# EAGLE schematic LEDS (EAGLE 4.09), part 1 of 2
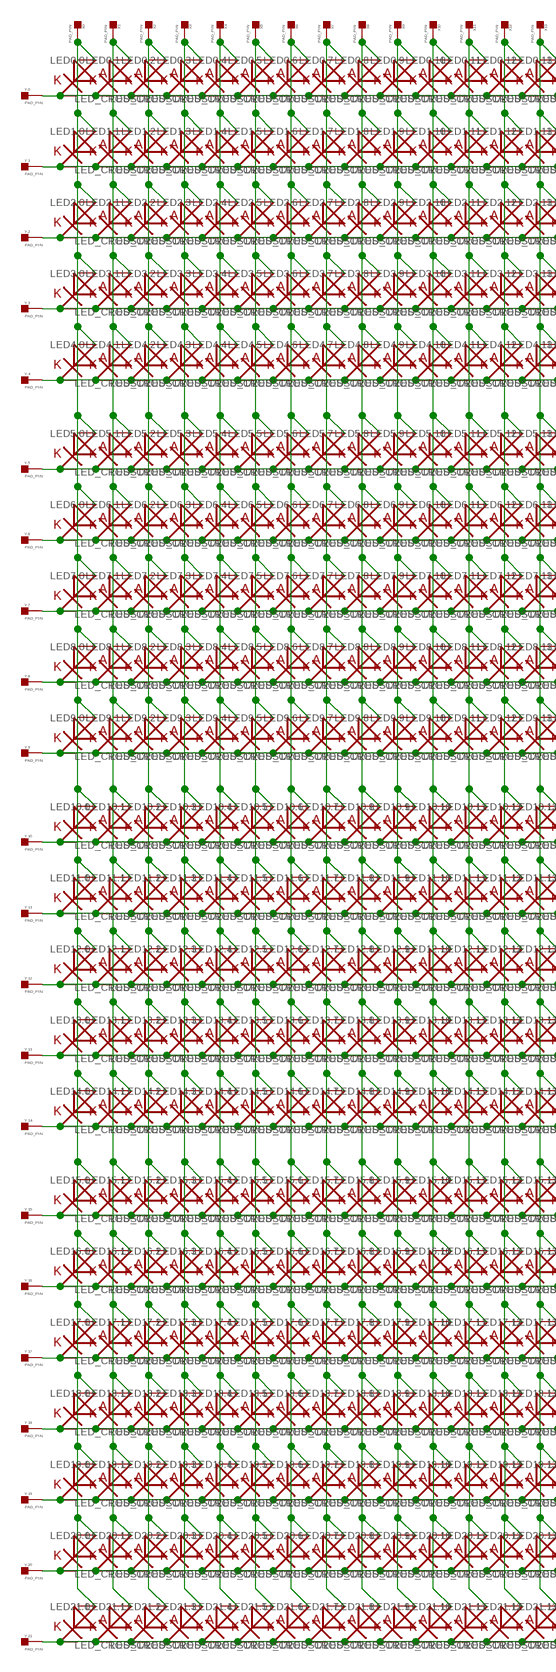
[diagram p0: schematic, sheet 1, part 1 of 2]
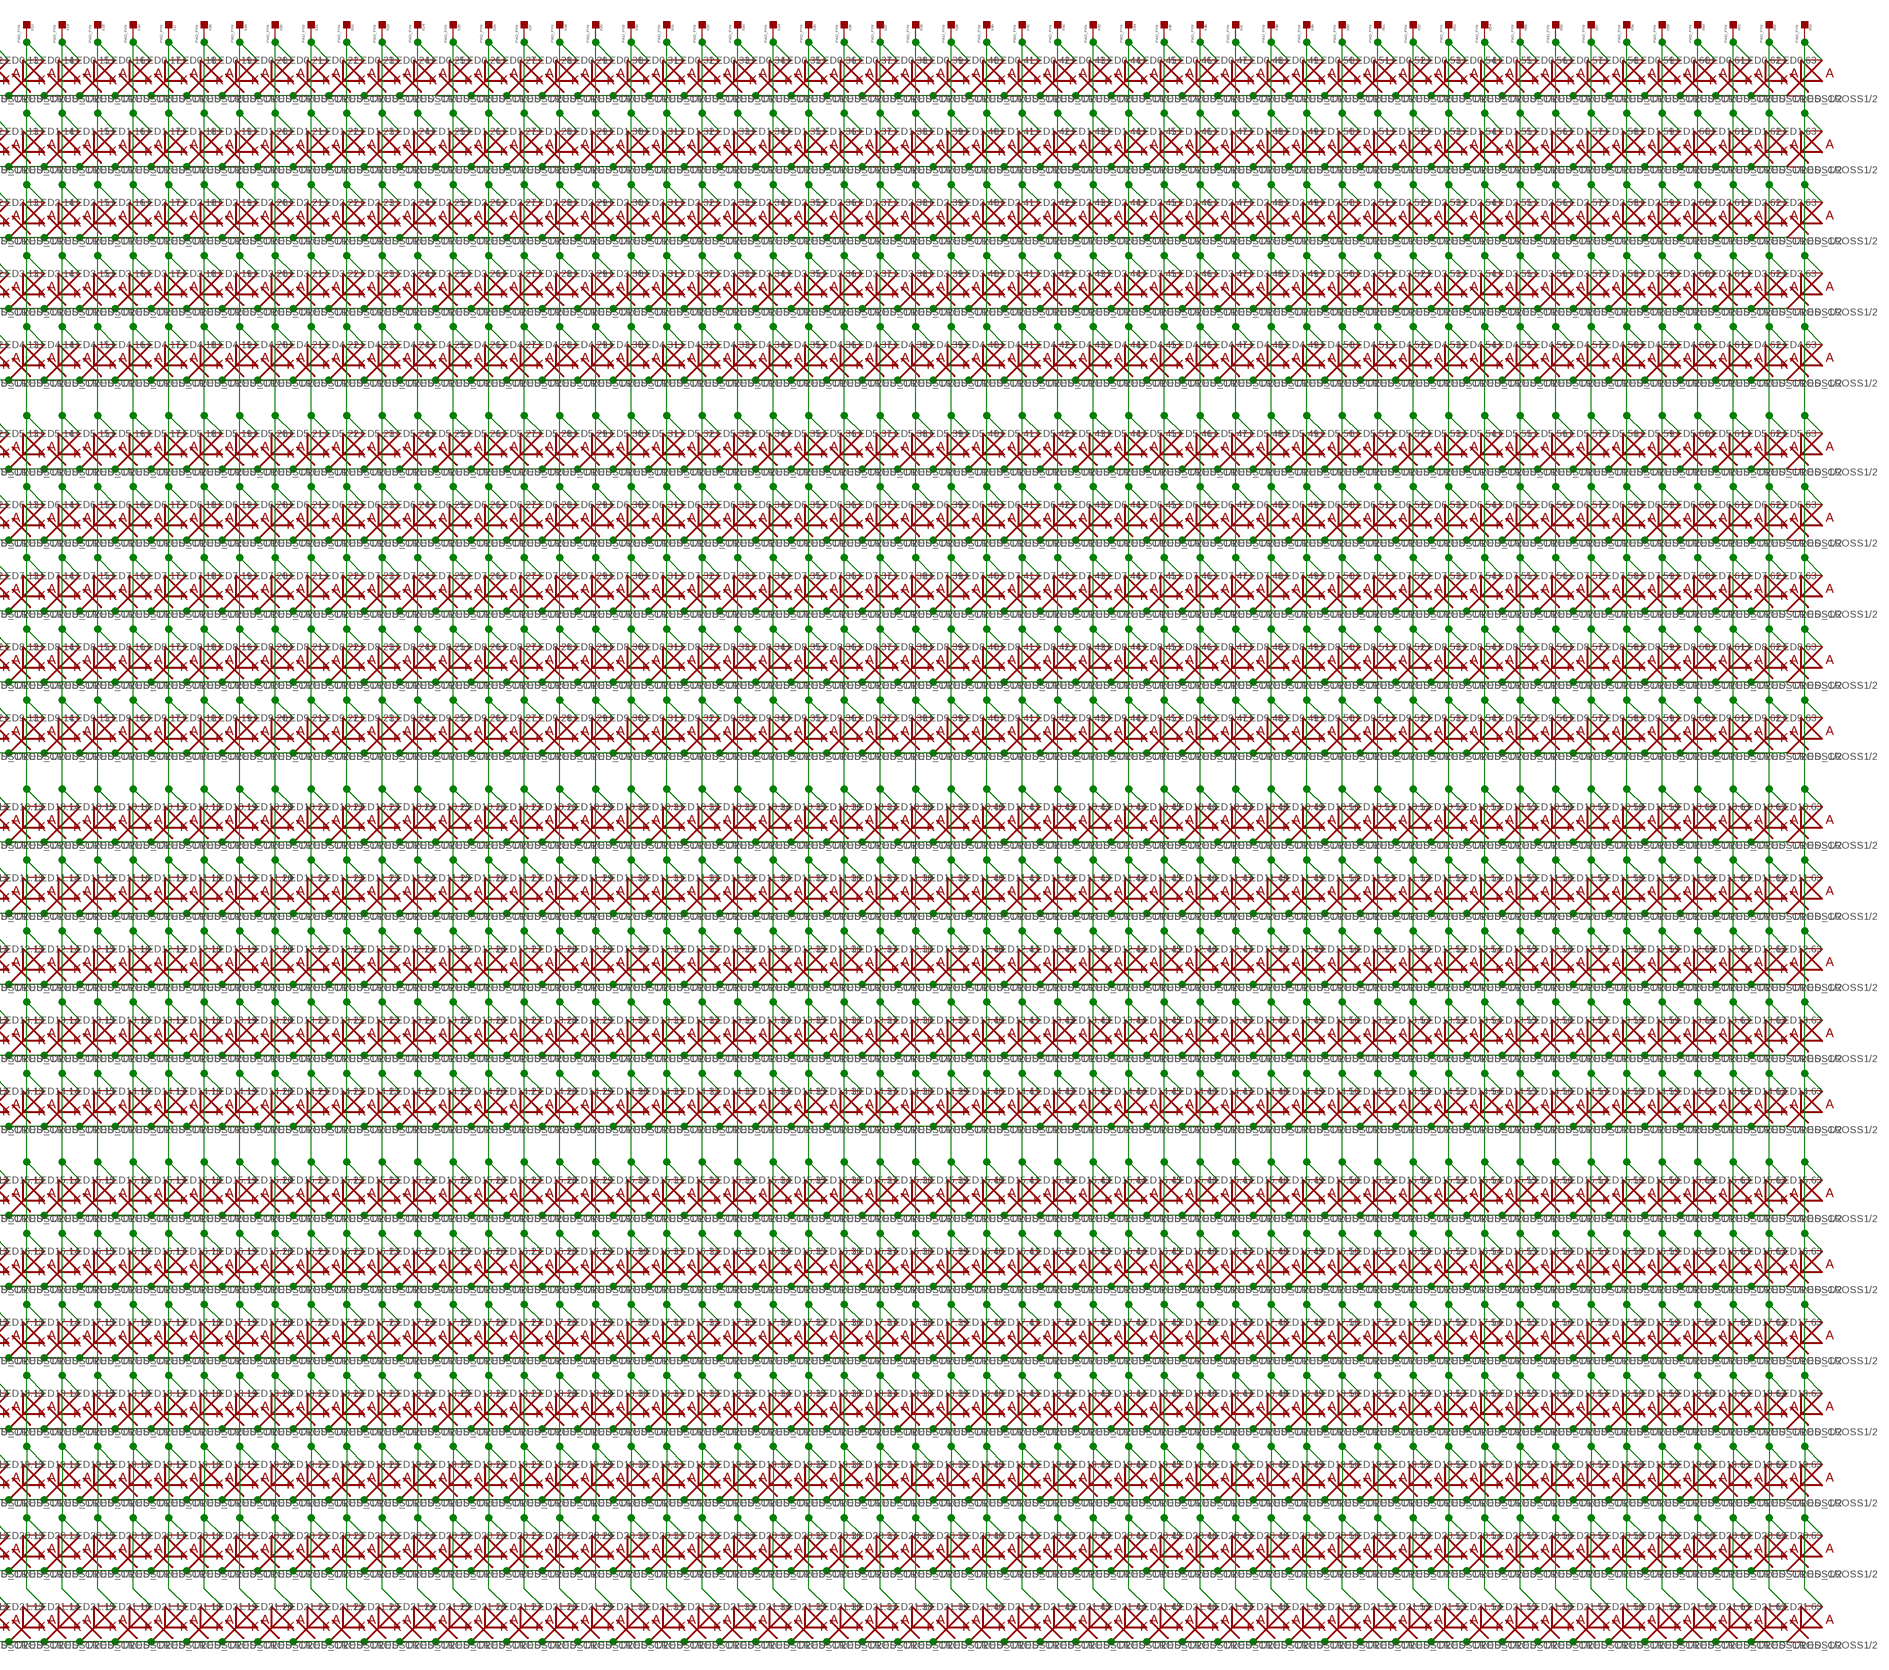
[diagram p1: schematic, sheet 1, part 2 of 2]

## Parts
LED0.0  LED_CROSS1/2  [LED_603]
LED0.1  LED_CROSS1/2  [LED_603]
LED0.2  LED_CROSS1/2  [LED_603]
LED0.3  LED_CROSS1/2  [LED_603]
LED0.4  LED_CROSS1/2  [LED_603]
LED0.5  LED_CROSS1/2  [LED_603]
LED0.6  LED_CROSS1/2  [LED_603]
LED0.7  LED_CROSS1/2  [LED_603]
LED0.8  LED_CROSS1/2  [LED_603]
LED0.9  LED_CROSS1/2  [LED_603]
LED0.10  LED_CROSS1/2  [LED_603]
LED0.11  LED_CROSS1/2  [LED_603]
LED0.12  LED_CROSS1/2  [LED_603]
LED0.13  LED_CROSS1/2  [LED_603]
LED0.14  LED_CROSS1/2  [LED_603]
LED0.15  LED_CROSS1/2  [LED_603]
LED0.16  LED_CROSS1/2  [LED_603]
LED0.17  LED_CROSS1/2  [LED_603]
LED0.18  LED_CROSS1/2  [LED_603]
LED0.19  LED_CROSS1/2  [LED_603]
LED0.20  LED_CROSS1/2  [LED_603]
LED0.21  LED_CROSS1/2  [LED_603]
LED0.22  LED_CROSS1/2  [LED_603]
LED0.23  LED_CROSS1/2  [LED_603]
LED0.24  LED_CROSS1/2  [LED_603]
LED0.25  LED_CROSS1/2  [LED_603]
LED0.26  LED_CROSS1/2  [LED_603]
LED0.27  LED_CROSS1/2  [LED_603]
LED0.28  LED_CROSS1/2  [LED_603]
LED0.29  LED_CROSS1/2  [LED_603]
LED0.30  LED_CROSS1/2  [LED_603]
LED0.31  LED_CROSS1/2  [LED_603]
LED0.32  LED_CROSS1/2  [LED_603]
LED0.33  LED_CROSS1/2  [LED_603]
LED0.34  LED_CROSS1/2  [LED_603]
LED0.35  LED_CROSS1/2  [LED_603]
LED0.36  LED_CROSS1/2  [LED_603]
LED0.37  LED_CROSS1/2  [LED_603]
LED0.38  LED_CROSS1/2  [LED_603]
LED0.39  LED_CROSS1/2  [LED_603]
LED0.40  LED_CROSS1/2  [LED_603]
LED0.41  LED_CROSS1/2  [LED_603]
LED0.42  LED_CROSS1/2  [LED_603]
LED0.43  LED_CROSS1/2  [LED_603]
LED0.44  LED_CROSS1/2  [LED_603]
LED0.45  LED_CROSS1/2  [LED_603]
LED0.46  LED_CROSS1/2  [LED_603]
LED0.47  LED_CROSS1/2  [LED_603]
LED0.48  LED_CROSS1/2  [LED_603]
LED0.49  LED_CROSS1/2  [LED_603]
LED0.50  LED_CROSS1/2  [LED_603]
LED0.51  LED_CROSS1/2  [LED_603]
LED0.52  LED_CROSS1/2  [LED_603]
LED0.53  LED_CROSS1/2  [LED_603]
LED0.54  LED_CROSS1/2  [LED_603]
LED0.55  LED_CROSS1/2  [LED_603]
LED0.56  LED_CROSS1/2  [LED_603]
LED0.57  LED_CROSS1/2  [LED_603]
LED0.58  LED_CROSS1/2  [LED_603]
LED0.59  LED_CROSS1/2  [LED_603]
LED0.60  LED_CROSS1/2  [LED_603]
LED0.61  LED_CROSS1/2  [LED_603]
LED0.62  LED_CROSS1/2  [LED_603]
LED0.63  LED_CROSS1/2  [LED_603]
LED1.0  LED_CROSS1/2  [LED_603]
LED1.1  LED_CROSS1/2  [LED_603]
LED1.2  LED_CROSS1/2  [LED_603]
LED1.3  LED_CROSS1/2  [LED_603]
LED1.4  LED_CROSS1/2  [LED_603]
LED1.5  LED_CROSS1/2  [LED_603]
LED1.6  LED_CROSS1/2  [LED_603]
LED1.7  LED_CROSS1/2  [LED_603]
LED1.8  LED_CROSS1/2  [LED_603]
LED1.9  LED_CROSS1/2  [LED_603]
LED1.10  LED_CROSS1/2  [LED_603]
LED1.11  LED_CROSS1/2  [LED_603]
LED1.12  LED_CROSS1/2  [LED_603]
LED1.13  LED_CROSS1/2  [LED_603]
LED1.14  LED_CROSS1/2  [LED_603]
LED1.15  LED_CROSS1/2  [LED_603]
LED1.16  LED_CROSS1/2  [LED_603]
LED1.17  LED_CROSS1/2  [LED_603]
LED1.18  LED_CROSS1/2  [LED_603]
LED1.19  LED_CROSS1/2  [LED_603]
LED1.20  LED_CROSS1/2  [LED_603]
LED1.21  LED_CROSS1/2  [LED_603]
LED1.22  LED_CROSS1/2  [LED_603]
LED1.23  LED_CROSS1/2  [LED_603]
LED1.24  LED_CROSS1/2  [LED_603]
LED1.25  LED_CROSS1/2  [LED_603]
LED1.26  LED_CROSS1/2  [LED_603]
LED1.27  LED_CROSS1/2  [LED_603]
LED1.28  LED_CROSS1/2  [LED_603]
LED1.29  LED_CROSS1/2  [LED_603]
LED1.30  LED_CROSS1/2  [LED_603]
LED1.31  LED_CROSS1/2  [LED_603]
LED1.32  LED_CROSS1/2  [LED_603]
LED1.33  LED_CROSS1/2  [LED_603]
LED1.34  LED_CROSS1/2  [LED_603]
LED1.35  LED_CROSS1/2  [LED_603]
LED1.36  LED_CROSS1/2  [LED_603]
LED1.37  LED_CROSS1/2  [LED_603]
LED1.38  LED_CROSS1/2  [LED_603]
LED1.39  LED_CROSS1/2  [LED_603]
LED1.40  LED_CROSS1/2  [LED_603]
LED1.41  LED_CROSS1/2  [LED_603]
LED1.42  LED_CROSS1/2  [LED_603]
LED1.43  LED_CROSS1/2  [LED_603]
LED1.44  LED_CROSS1/2  [LED_603]
LED1.45  LED_CROSS1/2  [LED_603]
LED1.46  LED_CROSS1/2  [LED_603]
LED1.47  LED_CROSS1/2  [LED_603]
LED1.48  LED_CROSS1/2  [LED_603]
LED1.49  LED_CROSS1/2  [LED_603]
LED1.50  LED_CROSS1/2  [LED_603]
LED1.51  LED_CROSS1/2  [LED_603]
LED1.52  LED_CROSS1/2  [LED_603]
LED1.53  LED_CROSS1/2  [LED_603]
LED1.54  LED_CROSS1/2  [LED_603]
LED1.55  LED_CROSS1/2  [LED_603]
LED1.56  LED_CROSS1/2  [LED_603]
LED1.57  LED_CROSS1/2  [LED_603]
LED1.58  LED_CROSS1/2  [LED_603]
LED1.59  LED_CROSS1/2  [LED_603]
LED1.60  LED_CROSS1/2  [LED_603]
LED1.61  LED_CROSS1/2  [LED_603]
LED1.62  LED_CROSS1/2  [LED_603]
LED1.63  LED_CROSS1/2  [LED_603]
LED2.0  LED_CROSS1/2  [LED_603]
LED2.1  LED_CROSS1/2  [LED_603]
LED2.2  LED_CROSS1/2  [LED_603]
LED2.3  LED_CROSS1/2  [LED_603]
LED2.4  LED_CROSS1/2  [LED_603]
LED2.5  LED_CROSS1/2  [LED_603]
LED2.6  LED_CROSS1/2  [LED_603]
LED2.7  LED_CROSS1/2  [LED_603]
LED2.8  LED_CROSS1/2  [LED_603]
LED2.9  LED_CROSS1/2  [LED_603]
LED2.10  LED_CROSS1/2  [LED_603]
LED2.11  LED_CROSS1/2  [LED_603]
LED2.12  LED_CROSS1/2  [LED_603]
LED2.13  LED_CROSS1/2  [LED_603]
LED2.14  LED_CROSS1/2  [LED_603]
LED2.15  LED_CROSS1/2  [LED_603]
LED2.16  LED_CROSS1/2  [LED_603]
LED2.17  LED_CROSS1/2  [LED_603]
LED2.18  LED_CROSS1/2  [LED_603]
LED2.19  LED_CROSS1/2  [LED_603]
LED2.20  LED_CROSS1/2  [LED_603]
LED2.21  LED_CROSS1/2  [LED_603]
LED2.22  LED_CROSS1/2  [LED_603]
LED2.23  LED_CROSS1/2  [LED_603]
LED2.24  LED_CROSS1/2  [LED_603]
LED2.25  LED_CROSS1/2  [LED_603]
LED2.26  LED_CROSS1/2  [LED_603]
LED2.27  LED_CROSS1/2  [LED_603]
LED2.28  LED_CROSS1/2  [LED_603]
LED2.29  LED_CROSS1/2  [LED_603]
LED2.30  LED_CROSS1/2  [LED_603]
LED2.31  LED_CROSS1/2  [LED_603]
LED2.32  LED_CROSS1/2  [LED_603]
LED2.33  LED_CROSS1/2  [LED_603]
LED2.34  LED_CROSS1/2  [LED_603]
LED2.35  LED_CROSS1/2  [LED_603]
LED2.36  LED_CROSS1/2  [LED_603]
LED2.37  LED_CROSS1/2  [LED_603]
LED2.38  LED_CROSS1/2  [LED_603]
LED2.39  LED_CROSS1/2  [LED_603]
LED2.40  LED_CROSS1/2  [LED_603]
LED2.41  LED_CROSS1/2  [LED_603]
LED2.42  LED_CROSS1/2  [LED_603]
LED2.43  LED_CROSS1/2  [LED_603]
LED2.44  LED_CROSS1/2  [LED_603]
LED2.45  LED_CROSS1/2  [LED_603]
LED2.46  LED_CROSS1/2  [LED_603]
LED2.47  LED_CROSS1/2  [LED_603]
LED2.48  LED_CROSS1/2  [LED_603]
LED2.49  LED_CROSS1/2  [LED_603]
LED2.50  LED_CROSS1/2  [LED_603]
LED2.51  LED_CROSS1/2  [LED_603]
LED2.52  LED_CROSS1/2  [LED_603]
LED2.53  LED_CROSS1/2  [LED_603]
LED2.54  LED_CROSS1/2  [LED_603]
LED2.55  LED_CROSS1/2  [LED_603]
LED2.56  LED_CROSS1/2  [LED_603]
LED2.57  LED_CROSS1/2  [LED_603]
LED2.58  LED_CROSS1/2  [LED_603]
LED2.59  LED_CROSS1/2  [LED_603]
LED2.60  LED_CROSS1/2  [LED_603]
LED2.61  LED_CROSS1/2  [LED_603]
LED2.62  LED_CROSS1/2  [LED_603]
LED2.63  LED_CROSS1/2  [LED_603]
LED3.0  LED_CROSS1/2  [LED_603]
LED3.1  LED_CROSS1/2  [LED_603]
LED3.2  LED_CROSS1/2  [LED_603]
LED3.3  LED_CROSS1/2  [LED_603]
LED3.4  LED_CROSS1/2  [LED_603]
LED3.5  LED_CROSS1/2  [LED_603]
LED3.6  LED_CROSS1/2  [LED_603]
LED3.7  LED_CROSS1/2  [LED_603]
LED3.8  LED_CROSS1/2  [LED_603]
LED3.9  LED_CROSS1/2  [LED_603]
LED3.10  LED_CROSS1/2  [LED_603]
LED3.11  LED_CROSS1/2  [LED_603]
LED3.12  LED_CROSS1/2  [LED_603]
LED3.13  LED_CROSS1/2  [LED_603]
LED3.14  LED_CROSS1/2  [LED_603]
LED3.15  LED_CROSS1/2  [LED_603]
LED3.16  LED_CROSS1/2  [LED_603]
LED3.17  LED_CROSS1/2  [LED_603]
LED3.18  LED_CROSS1/2  [LED_603]
LED3.19  LED_CROSS1/2  [LED_603]
LED3.20  LED_CROSS1/2  [LED_603]
LED3.21  LED_CROSS1/2  [LED_603]
LED3.22  LED_CROSS1/2  [LED_603]
LED3.23  LED_CROSS1/2  [LED_603]
LED3.24  LED_CROSS1/2  [LED_603]
LED3.25  LED_CROSS1/2  [LED_603]
LED3.26  LED_CROSS1/2  [LED_603]
LED3.27  LED_CROSS1/2  [LED_603]
LED3.28  LED_CROSS1/2  [LED_603]
LED3.29  LED_CROSS1/2  [LED_603]
LED3.30  LED_CROSS1/2  [LED_603]
LED3.31  LED_CROSS1/2  [LED_603]
LED3.32  LED_CROSS1/2  [LED_603]
LED3.33  LED_CROSS1/2  [LED_603]
LED3.34  LED_CROSS1/2  [LED_603]
LED3.35  LED_CROSS1/2  [LED_603]
LED3.36  LED_CROSS1/2  [LED_603]
LED3.37  LED_CROSS1/2  [LED_603]
LED3.38  LED_CROSS1/2  [LED_603]
LED3.39  LED_CROSS1/2  [LED_603]
LED3.40  LED_CROSS1/2  [LED_603]
LED3.41  LED_CROSS1/2  [LED_603]
LED3.42  LED_CROSS1/2  [LED_603]
LED3.43  LED_CROSS1/2  [LED_603]
LED3.44  LED_CROSS1/2  [LED_603]
LED3.45  LED_CROSS1/2  [LED_603]
LED3.46  LED_CROSS1/2  [LED_603]
LED3.47  LED_CROSS1/2  [LED_603]
LED3.48  LED_CROSS1/2  [LED_603]
LED3.49  LED_CROSS1/2  [LED_603]
LED3.50  LED_CROSS1/2  [LED_603]
LED3.51  LED_CROSS1/2  [LED_603]
LED3.52  LED_CROSS1/2  [LED_603]
LED3.53  LED_CROSS1/2  [LED_603]
LED3.54  LED_CROSS1/2  [LED_603]
LED3.55  LED_CROSS1/2  [LED_603]
LED3.56  LED_CROSS1/2  [LED_603]
LED3.57  LED_CROSS1/2  [LED_603]
LED3.58  LED_CROSS1/2  [LED_603]
LED3.59  LED_CROSS1/2  [LED_603]
LED3.60  LED_CROSS1/2  [LED_603]
LED3.61  LED_CROSS1/2  [LED_603]
LED3.62  LED_CROSS1/2  [LED_603]
LED3.63  LED_CROSS1/2  [LED_603]
LED4.0  LED_CROSS1/2  [LED_603]
LED4.1  LED_CROSS1/2  [LED_603]
LED4.2  LED_CROSS1/2  [LED_603]
LED4.3  LED_CROSS1/2  [LED_603]
LED4.4  LED_CROSS1/2  [LED_603]
LED4.5  LED_CROSS1/2  [LED_603]
LED4.6  LED_CROSS1/2  [LED_603]
LED4.7  LED_CROSS1/2  [LED_603]
LED4.8  LED_CROSS1/2  [LED_603]
LED4.9  LED_CROSS1/2  [LED_603]
LED4.10  LED_CROSS1/2  [LED_603]
LED4.11  LED_CROSS1/2  [LED_603]
LED4.12  LED_CROSS1/2  [LED_603]
LED4.13  LED_CROSS1/2  [LED_603]
LED4.14  LED_CROSS1/2  [LED_603]
LED4.15  LED_CROSS1/2  [LED_603]
LED4.16  LED_CROSS1/2  [LED_603]
LED4.17  LED_CROSS1/2  [LED_603]
LED4.18  LED_CROSS1/2  [LED_603]
LED4.19  LED_CROSS1/2  [LED_603]
LED4.20  LED_CROSS1/2  [LED_603]
LED4.21  LED_CROSS1/2  [LED_603]
LED4.22  LED_CROSS1/2  [LED_603]
LED4.23  LED_CROSS1/2  [LED_603]
LED4.24  LED_CROSS1/2  [LED_603]
LED4.25  LED_CROSS1/2  [LED_603]
LED4.26  LED_CROSS1/2  [LED_603]
LED4.27  LED_CROSS1/2  [LED_603]
LED4.28  LED_CROSS1/2  [LED_603]
LED4.29  LED_CROSS1/2  [LED_603]
LED4.30  LED_CROSS1/2  [LED_603]
LED4.31  LED_CROSS1/2  [LED_603]
LED4.32  LED_CROSS1/2  [LED_603]
LED4.33  LED_CROSS1/2  [LED_603]
LED4.34  LED_CROSS1/2  [LED_603]
LED4.35  LED_CROSS1/2  [LED_603]
LED4.36  LED_CROSS1/2  [LED_603]
LED4.37  LED_CROSS1/2  [LED_603]
LED4.38  LED_CROSS1/2  [LED_603]
LED4.39  LED_CROSS1/2  [LED_603]
LED4.40  LED_CROSS1/2  [LED_603]
LED4.41  LED_CROSS1/2  [LED_603]
LED4.42  LED_CROSS1/2  [LED_603]
LED4.43  LED_CROSS1/2  [LED_603]
LED4.44  LED_CROSS1/2  [LED_603]
LED4.45  LED_CROSS1/2  [LED_603]
LED4.46  LED_CROSS1/2  [LED_603]
LED4.47  LED_CROSS1/2  [LED_603]
LED4.48  LED_CROSS1/2  [LED_603]
LED4.49  LED_CROSS1/2  [LED_603]
LED4.50  LED_CROSS1/2  [LED_603]
LED4.51  LED_CROSS1/2  [LED_603]
LED4.52  LED_CROSS1/2  [LED_603]
LED4.53  LED_CROSS1/2  [LED_603]
LED4.54  LED_CROSS1/2  [LED_603]
LED4.55  LED_CROSS1/2  [LED_603]
LED4.56  LED_CROSS1/2  [LED_603]
LED4.57  LED_CROSS1/2  [LED_603]
LED4.58  LED_CROSS1/2  [LED_603]
LED4.59  LED_CROSS1/2  [LED_603]
LED4.60  LED_CROSS1/2  [LED_603]
LED4.61  LED_CROSS1/2  [LED_603]
LED4.62  LED_CROSS1/2  [LED_603]
LED4.63  LED_CROSS1/2  [LED_603]
LED5.0  LED_CROSS1/2  [LED_603]
LED5.1  LED_CROSS1/2  [LED_603]
LED5.2  LED_CROSS1/2  [LED_603]
LED5.3  LED_CROSS1/2  [LED_603]
LED5.4  LED_CROSS1/2  [LED_603]
LED5.5  LED_CROSS1/2  [LED_603]
LED5.6  LED_CROSS1/2  [LED_603]
LED5.7  LED_CROSS1/2  [LED_603]
LED5.8  LED_CROSS1/2  [LED_603]
LED5.9  LED_CROSS1/2  [LED_603]
LED5.10  LED_CROSS1/2  [LED_603]
LED5.11  LED_CROSS1/2  [LED_603]
LED5.12  LED_CROSS1/2  [LED_603]
LED5.13  LED_CROSS1/2  [LED_603]
LED5.14  LED_CROSS1/2  [LED_603]
LED5.15  LED_CROSS1/2  [LED_603]
LED5.16  LED_CROSS1/2  [LED_603]
LED5.17  LED_CROSS1/2  [LED_603]
LED5.18  LED_CROSS1/2  [LED_603]
LED5.19  LED_CROSS1/2  [LED_603]
LED5.20  LED_CROSS1/2  [LED_603]
LED5.21  LED_CROSS1/2  [LED_603]
LED5.22  LED_CROSS1/2  [LED_603]
LED5.23  LED_CROSS1/2  [LED_603]
LED5.24  LED_CROSS1/2  [LED_603]
LED5.25  LED_CROSS1/2  [LED_603]
LED5.26  LED_CROSS1/2  [LED_603]
LED5.27  LED_CROSS1/2  [LED_603]
LED5.28  LED_CROSS1/2  [LED_603]
LED5.29  LED_CROSS1/2  [LED_603]
LED5.30  LED_CROSS1/2  [LED_603]
LED5.31  LED_CROSS1/2  [LED_603]
LED5.32  LED_CROSS1/2  [LED_603]
LED5.33  LED_CROSS1/2  [LED_603]
LED5.34  LED_CROSS1/2  [LED_603]
LED5.35  LED_CROSS1/2  [LED_603]
LED5.36  LED_CROSS1/2  [LED_603]
LED5.37  LED_CROSS1/2  [LED_603]
LED5.38  LED_CROSS1/2  [LED_603]
LED5.39  LED_CROSS1/2  [LED_603]
LED5.40  LED_CROSS1/2  [LED_603]
LED5.41  LED_CROSS1/2  [LED_603]
LED5.42  LED_CROSS1/2  [LED_603]
LED5.43  LED_CROSS1/2  [LED_603]
LED5.44  LED_CROSS1/2  [LED_603]
LED5.45  LED_CROSS1/2  [LED_603]
LED5.46  LED_CROSS1/2  [LED_603]
LED5.47  LED_CROSS1/2  [LED_603]
LED5.48  LED_CROSS1/2  [LED_603]
LED5.49  LED_CROSS1/2  [LED_603]
LED5.50  LED_CROSS1/2  [LED_603]
LED5.51  LED_CROSS1/2  [LED_603]
LED5.52  LED_CROSS1/2  [LED_603]
LED5.53  LED_CROSS1/2  [LED_603]
LED5.54  LED_CROSS1/2  [LED_603]
LED5.55  LED_CROSS1/2  [LED_603]
LED5.56  LED_CROSS1/2  [LED_603]
LED5.57  LED_CROSS1/2  [LED_603]
LED5.58  LED_CROSS1/2  [LED_603]
LED5.59  LED_CROSS1/2  [LED_603]
LED5.60  LED_CROSS1/2  [LED_603]
LED5.61  LED_CROSS1/2  [LED_603]
LED5.62  LED_CROSS1/2  [LED_603]
LED5.63  LED_CROSS1/2  [LED_603]
LED6.0  LED_CROSS1/2  [LED_603]
LED6.1  LED_CROSS1/2  [LED_603]
LED6.2  LED_CROSS1/2  [LED_603]
LED6.3  LED_CROSS1/2  [LED_603]
LED6.4  LED_CROSS1/2  [LED_603]
LED6.5  LED_CROSS1/2  [LED_603]
LED6.6  LED_CROSS1/2  [LED_603]
LED6.7  LED_CROSS1/2  [LED_603]
LED6.8  LED_CROSS1/2  [LED_603]
LED6.9  LED_CROSS1/2  [LED_603]
LED6.10  LED_CROSS1/2  [LED_603]
LED6.11  LED_CROSS1/2  [LED_603]
LED6.12  LED_CROSS1/2  [LED_603]
LED6.13  LED_CROSS1/2  [LED_603]
LED6.14  LED_CROSS1/2  [LED_603]
LED6.15  LED_CROSS1/2  [LED_603]
LED6.16  LED_CROSS1/2  [LED_603]
LED6.17  LED_CROSS1/2  [LED_603]
LED6.18  LED_CROSS1/2  [LED_603]
LED6.19  LED_CROSS1/2  [LED_603]
LED6.20  LED_CROSS1/2  [LED_603]
LED6.21  LED_CROSS1/2  [LED_603]
LED6.22  LED_CROSS1/2  [LED_603]
LED6.23  LED_CROSS1/2  [LED_603]
LED6.24  LED_CROSS1/2  [LED_603]
LED6.25  LED_CROSS1/2  [LED_603]
LED6.26  LED_CROSS1/2  [LED_603]
LED6.27  LED_CROSS1/2  [LED_603]
LED6.28  LED_CROSS1/2  [LED_603]
LED6.29  LED_CROSS1/2  [LED_603]
LED6.30  LED_CROSS1/2  [LED_603]
LED6.31  LED_CROSS1/2  [LED_603]
LED6.32  LED_CROSS1/2  [LED_603]
LED6.33  LED_CROSS1/2  [LED_603]
LED6.34  LED_CROSS1/2  [LED_603]
LED6.35  LED_CROSS1/2  [LED_603]
LED6.36  LED_CROSS1/2  [LED_603]
LED6.37  LED_CROSS1/2  [LED_603]
LED6.38  LED_CROSS1/2  [LED_603]
LED6.39  LED_CROSS1/2  [LED_603]
LED6.40  LED_CROSS1/2  [LED_603]
LED6.41  LED_CROSS1/2  [LED_603]
LED6.42  LED_CROSS1/2  [LED_603]
LED6.43  LED_CROSS1/2  [LED_603]
LED6.44  LED_CROSS1/2  [LED_603]
LED6.45  LED_CROSS1/2  [LED_603]
LED6.46  LED_CROSS1/2  [LED_603]
LED6.47  LED_CROSS1/2  [LED_603]
LED6.48  LED_CROSS1/2  [LED_603]
LED6.49  LED_CROSS1/2  [LED_603]
LED6.50  LED_CROSS1/2  [LED_603]
LED6.51  LED_CROSS1/2  [LED_603]
LED6.52  LED_CROSS1/2  [LED_603]
LED6.53  LED_CROSS1/2  [LED_603]
LED6.54  LED_CROSS1/2  [LED_603]
LED6.55  LED_CROSS1/2  [LED_603]
LED6.56  LED_CROSS1/2  [LED_603]
LED6.57  LED_CROSS1/2  [LED_603]
LED6.58  LED_CROSS1/2  [LED_603]
LED6.59  LED_CROSS1/2  [LED_603]
LED6.60  LED_CROSS1/2  [LED_603]
LED6.61  LED_CROSS1/2  [LED_603]
LED6.62  LED_CROSS1/2  [LED_603]
LED6.63  LED_CROSS1/2  [LED_603]
LED7.0  LED_CROSS1/2  [LED_603]
LED7.1  LED_CROSS1/2  [LED_603]
LED7.2  LED_CROSS1/2  [LED_603]
LED7.3  LED_CROSS1/2  [LED_603]
LED7.4  LED_CROSS1/2  [LED_603]
LED7.5  LED_CROSS1/2  [LED_603]
LED7.6  LED_CROSS1/2  [LED_603]
LED7.7  LED_CROSS1/2  [LED_603]
LED7.8  LED_CROSS1/2  [LED_603]
LED7.9  LED_CROSS1/2  [LED_603]
LED7.10  LED_CROSS1/2  [LED_603]
LED7.11  LED_CROSS1/2  [LED_603]
LED7.12  LED_CROSS1/2  [LED_603]
LED7.13  LED_CROSS1/2  [LED_603]
LED7.14  LED_CROSS1/2  [LED_603]
LED7.15  LED_CROSS1/2  [LED_603]
LED7.16  LED_CROSS1/2  [LED_603]
LED7.17  LED_CROSS1/2  [LED_603]
LED7.18  LED_CROSS1/2  [LED_603]
LED7.19  LED_CROSS1/2  [LED_603]
LED7.20  LED_CROSS1/2  [LED_603]
LED7.21  LED_CROSS1/2  [LED_603]
LED7.22  LED_CROSS1/2  [LED_603]
LED7.23  LED_CROSS1/2  [LED_603]
LED7.24  LED_CROSS1/2  [LED_603]
LED7.25  LED_CROSS1/2  [LED_603]
LED7.26  LED_CROSS1/2  [LED_603]
LED7.27  LED_CROSS1/2  [LED_603]
LED7.28  LED_CROSS1/2  [LED_603]
LED7.29  LED_CROSS1/2  [LED_603]
LED7.30  LED_CROSS1/2  [LED_603]
LED7.31  LED_CROSS1/2  [LED_603]
LED7.32  LED_CROSS1/2  [LED_603]
LED7.33  LED_CROSS1/2  [LED_603]
LED7.34  LED_CROSS1/2  [LED_603]
LED7.35  LED_CROSS1/2  [LED_603]
LED7.36  LED_CROSS1/2  [LED_603]
LED7.37  LED_CROSS1/2  [LED_603]
LED7.38  LED_CROSS1/2  [LED_603]
LED7.39  LED_CROSS1/2  [LED_603]
LED7.40  LED_CROSS1/2  [LED_603]
LED7.41  LED_CROSS1/2  [LED_603]
LED7.42  LED_CROSS1/2  [LED_603]
LED7.43  LED_CROSS1/2  [LED_603]
LED7.44  LED_CROSS1/2  [LED_603]
LED7.45  LED_CROSS1/2  [LED_603]
LED7.46  LED_CROSS1/2  [LED_603]
LED7.47  LED_CROSS1/2  [LED_603]
LED7.48  LED_CROSS1/2  [LED_603]
LED7.49  LED_CROSS1/2  [LED_603]
LED7.50  LED_CROSS1/2  [LED_603]
LED7.51  LED_CROSS1/2  [LED_603]
LED7.52  LED_CROSS1/2  [LED_603]
LED7.53  LED_CROSS1/2  [LED_603]
LED7.54  LED_CROSS1/2  [LED_603]
LED7.55  LED_CROSS1/2  [LED_603]
LED7.56  LED_CROSS1/2  [LED_603]
LED7.57  LED_CROSS1/2  [LED_603]
LED7.58  LED_CROSS1/2  [LED_603]
LED7.59  LED_CROSS1/2  [LED_603]
LED7.60  LED_CROSS1/2  [LED_603]
LED7.61  LED_CROSS1/2  [LED_603]
LED7.62  LED_CROSS1/2  [LED_603]
LED7.63  LED_CROSS1/2  [LED_603]
LED8.0  LED_CROSS1/2  [LED_603]
LED8.1  LED_CROSS1/2  [LED_603]
LED8.2  LED_CROSS1/2  [LED_603]
LED8.3  LED_CROSS1/2  [LED_603]
LED8.4  LED_CROSS1/2  [LED_603]
LED8.5  LED_CROSS1/2  [LED_603]
LED8.6  LED_CROSS1/2  [LED_603]
LED8.7  LED_CROSS1/2  [LED_603]
LED8.8  LED_CROSS1/2  [LED_603]
LED8.9  LED_CROSS1/2  [LED_603]
LED8.10  LED_CROSS1/2  [LED_603]
LED8.11  LED_CROSS1/2  [LED_603]
LED8.12  LED_CROSS1/2  [LED_603]
LED8.13  LED_CROSS1/2  [LED_603]
LED8.14  LED_CROSS1/2  [LED_603]
LED8.15  LED_CROSS1/2  [LED_603]
LED8.16  LED_CROSS1/2  [LED_603]
LED8.17  LED_CROSS1/2  [LED_603]
LED8.18  LED_CROSS1/2  [LED_603]
LED8.19  LED_CROSS1/2  [LED_603]
LED8.20  LED_CROSS1/2  [LED_603]
LED8.21  LED_CROSS1/2  [LED_603]
LED8.22  LED_CROSS1/2  [LED_603]
LED8.23  LED_CROSS1/2  [LED_603]
LED8.24  LED_CROSS1/2  [LED_603]
LED8.25  LED_CROSS1/2  [LED_603]
LED8.26  LED_CROSS1/2  [LED_603]
LED8.27  LED_CROSS1/2  [LED_603]
LED8.28  LED_CROSS1/2  [LED_603]
LED8.29  LED_CROSS1/2  [LED_603]
LED8.30  LED_CROSS1/2  [LED_603]
LED8.31  LED_CROSS1/2  [LED_603]
LED8.32  LED_CROSS1/2  [LED_603]
LED8.33  LED_CROSS1/2  [LED_603]
LED8.34  LED_CROSS1/2  [LED_603]
LED8.35  LED_CROSS1/2  [LED_603]
LED8.36  LED_CROSS1/2  [LED_603]
LED8.37  LED_CROSS1/2  [LED_603]
LED8.38  LED_CROSS1/2  [LED_603]
LED8.39  LED_CROSS1/2  [LED_603]
LED8.40  LED_CROSS1/2  [LED_603]
LED8.41  LED_CROSS1/2  [LED_603]
LED8.42  LED_CROSS1/2  [LED_603]
LED8.43  LED_CROSS1/2  [LED_603]
LED8.44  LED_CROSS1/2  [LED_603]
LED8.45  LED_CROSS1/2  [LED_603]
LED8.46  LED_CROSS1/2  [LED_603]
LED8.47  LED_CROSS1/2  [LED_603]
LED8.48  LED_CROSS1/2  [LED_603]
LED8.49  LED_CROSS1/2  [LED_603]
LED8.50  LED_CROSS1/2  [LED_603]
LED8.51  LED_CROSS1/2  [LED_603]
LED8.52  LED_CROSS1/2  [LED_603]
LED8.53  LED_CROSS1/2  [LED_603]
LED8.54  LED_CROSS1/2  [LED_603]
LED8.55  LED_CROSS1/2  [LED_603]
LED8.56  LED_CROSS1/2  [LED_603]
LED8.57  LED_CROSS1/2  [LED_603]
LED8.58  LED_CROSS1/2  [LED_603]
LED8.59  LED_CROSS1/2  [LED_603]
LED8.60  LED_CROSS1/2  [LED_603]
LED8.61  LED_CROSS1/2  [LED_603]
LED8.62  LED_CROSS1/2  [LED_603]
LED8.63  LED_CROSS1/2  [LED_603]
LED9.0  LED_CROSS1/2  [LED_603]
LED9.1  LED_CROSS1/2  [LED_603]
LED9.2  LED_CROSS1/2  [LED_603]
LED9.3  LED_CROSS1/2  [LED_603]
LED9.4  LED_CROSS1/2  [LED_603]
LED9.5  LED_CROSS1/2  [LED_603]
LED9.6  LED_CROSS1/2  [LED_603]
LED9.7  LED_CROSS1/2  [LED_603]
LED9.8  LED_CROSS1/2  [LED_603]
LED9.9  LED_CROSS1/2  [LED_603]
LED9.10  LED_CROSS1/2  [LED_603]
LED9.11  LED_CROSS1/2  [LED_603]
LED9.12  LED_CROSS1/2  [LED_603]
LED9.13  LED_CROSS1/2  [LED_603]
LED9.14  LED_CROSS1/2  [LED_603]
LED9.15  LED_CROSS1/2  [LED_603]
LED9.16  LED_CROSS1/2  [LED_603]
LED9.17  LED_CROSS1/2  [LED_603]
LED9.18  LED_CROSS1/2  [LED_603]
LED9.19  LED_CROSS1/2  [LED_603]
LED9.20  LED_CROSS1/2  [LED_603]
LED9.21  LED_CROSS1/2  [LED_603]
LED9.22  LED_CROSS1/2  [LED_603]
LED9.23  LED_CROSS1/2  [LED_603]
LED9.24  LED_CROSS1/2  [LED_603]
LED9.25  LED_CROSS1/2  [LED_603]
LED9.26  LED_CROSS1/2  [LED_603]
LED9.27  LED_CROSS1/2  [LED_603]
LED9.28  LED_CROSS1/2  [LED_603]
LED9.29  LED_CROSS1/2  [LED_603]
LED9.30  LED_CROSS1/2  [LED_603]
LED9.31  LED_CROSS1/2  [LED_603]
LED9.32  LED_CROSS1/2  [LED_603]
LED9.33  LED_CROSS1/2  [LED_603]
LED9.34  LED_CROSS1/2  [LED_603]
LED9.35  LED_CROSS1/2  [LED_603]
LED9.36  LED_CROSS1/2  [LED_603]
LED9.37  LED_CROSS1/2  [LED_603]
LED9.38  LED_CROSS1/2  [LED_603]
LED9.39  LED_CROSS1/2  [LED_603]
LED9.40  LED_CROSS1/2  [LED_603]
LED9.41  LED_CROSS1/2  [LED_603]
LED9.42  LED_CROSS1/2  [LED_603]
LED9.43  LED_CROSS1/2  [LED_603]
LED9.44  LED_CROSS1/2  [LED_603]
LED9.45  LED_CROSS1/2  [LED_603]
LED9.46  LED_CROSS1/2  [LED_603]
LED9.47  LED_CROSS1/2  [LED_603]
LED9.48  LED_CROSS1/2  [LED_603]
LED9.49  LED_CROSS1/2  [LED_603]
LED9.50  LED_CROSS1/2  [LED_603]
LED9.51  LED_CROSS1/2  [LED_603]
LED9.52  LED_CROSS1/2  [LED_603]
LED9.53  LED_CROSS1/2  [LED_603]
LED9.54  LED_CROSS1/2  [LED_603]
LED9.55  LED_CROSS1/2  [LED_603]
LED9.56  LED_CROSS1/2  [LED_603]
LED9.57  LED_CROSS1/2  [LED_603]
LED9.58  LED_CROSS1/2  [LED_603]
LED9.59  LED_CROSS1/2  [LED_603]
LED9.60  LED_CROSS1/2  [LED_603]
LED9.61  LED_CROSS1/2  [LED_603]
LED9.62  LED_CROSS1/2  [LED_603]
LED9.63  LED_CROSS1/2  [LED_603]
LED10.0  LED_CROSS1/2  [LED_603]
LED10.1  LED_CROSS1/2  [LED_603]
LED10.2  LED_CROSS1/2  [LED_603]
LED10.3  LED_CROSS1/2  [LED_603]
LED10.4  LED_CROSS1/2  [LED_603]
LED10.5  LED_CROSS1/2  [LED_603]
LED10.6  LED_CROSS1/2  [LED_603]
LED10.7  LED_CROSS1/2  [LED_603]
LED10.8  LED_CROSS1/2  [LED_603]
LED10.9  LED_CROSS1/2  [LED_603]
LED10.10  LED_CROSS1/2  [LED_603]
LED10.11  LED_CROSS1/2  [LED_603]
LED10.12  LED_CROSS1/2  [LED_603]
LED10.13  LED_CROSS1/2  [LED_603]
LED10.14  LED_CROSS1/2  [LED_603]
LED10.15  LED_CROSS1/2  [LED_603]
LED10.16  LED_CROSS1/2  [LED_603]
LED10.17  LED_CROSS1/2  [LED_603]
LED10.18  LED_CROSS1/2  [LED_603]
LED10.19  LED_CROSS1/2  [LED_603]
LED10.20  LED_CROSS1/2  [LED_603]
LED10.21  LED_CROSS1/2  [LED_603]
LED10.22  LED_CROSS1/2  [LED_603]
LED10.23  LED_CROSS1/2  [LED_603]
LED10.24  LED_CROSS1/2  [LED_603]
LED10.25  LED_CROSS1/2  [LED_603]
LED10.26  LED_CROSS1/2  [LED_603]
LED10.27  LED_CROSS1/2  [LED_603]
LED10.28  LED_CROSS1/2  [LED_603]
LED10.29  LED_CROSS1/2  [LED_603]
LED10.30  LED_CROSS1/2  [LED_603]
LED10.31  LED_CROSS1/2  [LED_603]
LED10.32  LED_CROSS1/2  [LED_603]
LED10.33  LED_CROSS1/2  [LED_603]
LED10.34  LED_CROSS1/2  [LED_603]
LED10.35  LED_CROSS1/2  [LED_603]
LED10.36  LED_CROSS1/2  [LED_603]
LED10.37  LED_CROSS1/2  [LED_603]
LED10.38  LED_CROSS1/2  [LED_603]
LED10.39  LED_CROSS1/2  [LED_603]
LED10.40  LED_CROSS1/2  [LED_603]
LED10.41  LED_CROSS1/2  [LED_603]
LED10.42  LED_CROSS1/2  [LED_603]
LED10.43  LED_CROSS1/2  [LED_603]
LED10.44  LED_CROSS1/2  [LED_603]
LED10.45  LED_CROSS1/2  [LED_603]
LED10.46  LED_CROSS1/2  [LED_603]
LED10.47  LED_CROSS1/2  [LED_603]
LED10.48  LED_CROSS1/2  [LED_603]
LED10.49  LED_CROSS1/2  [LED_603]
LED10.50  LED_CROSS1/2  [LED_603]
LED10.51  LED_CROSS1/2  [LED_603]
LED10.52  LED_CROSS1/2  [LED_603]
LED10.53  LED_CROSS1/2  [LED_603]
LED10.54  LED_CROSS1/2  [LED_603]
LED10.55  LED_CROSS1/2  [LED_603]
LED10.56  LED_CROSS1/2  [LED_603]
LED10.57  LED_CROSS1/2  [LED_603]
LED10.58  LED_CROSS1/2  [LED_603]
LED10.59  LED_CROSS1/2  [LED_603]
LED10.60  LED_CROSS1/2  [LED_603]
LED10.61  LED_CROSS1/2  [LED_603]
LED10.62  LED_CROSS1/2  [LED_603]
LED10.63  LED_CROSS1/2  [LED_603]
LED11.0  LED_CROSS1/2  [LED_603]
LED11.1  LED_CROSS1/2  [LED_603]
LED11.2  LED_CROSS1/2  [LED_603]
LED11.3  LED_CROSS1/2  [LED_603]
LED11.4  LED_CROSS1/2  [LED_603]
LED11.5  LED_CROSS1/2  [LED_603]
LED11.6  LED_CROSS1/2  [LED_603]
LED11.7  LED_CROSS1/2  [LED_603]
LED11.8  LED_CROSS1/2  [LED_603]
LED11.9  LED_CROSS1/2  [LED_603]
LED11.10  LED_CROSS1/2  [LED_603]
LED11.11  LED_CROSS1/2  [LED_603]
LED11.12  LED_CROSS1/2  [LED_603]
LED11.13  LED_CROSS1/2  [LED_603]
LED11.14  LED_CROSS1/2  [LED_603]
LED11.15  LED_CROSS1/2  [LED_603]
LED11.16  LED_CROSS1/2  [LED_603]
LED11.17  LED_CROSS1/2  [LED_603]
LED11.18  LED_CROSS1/2  [LED_603]
LED11.19  LED_CROSS1/2  [LED_603]
LED11.20  LED_CROSS1/2  [LED_603]
LED11.21  LED_CROSS1/2  [LED_603]
LED11.22  LED_CROSS1/2  [LED_603]
LED11.23  LED_CROSS1/2  [LED_603]
LED11.24  LED_CROSS1/2  [LED_603]
LED11.25  LED_CROSS1/2  [LED_603]
LED11.26  LED_CROSS1/2  [LED_603]
LED11.27  LED_CROSS1/2  [LED_603]
LED11.28  LED_CROSS1/2  [LED_603]
LED11.29  LED_CROSS1/2  [LED_603]
LED11.30  LED_CROSS1/2  [LED_603]
LED11.31  LED_CROSS1/2  [LED_603]
LED11.32  LED_CROSS1/2  [LED_603]
LED11.33  LED_CROSS1/2  [LED_603]
LED11.34  LED_CROSS1/2  [LED_603]
LED11.35  LED_CROSS1/2  [LED_603]
LED11.36  LED_CROSS1/2  [LED_603]
LED11.37  LED_CROSS1/2  [LED_603]
LED11.38  LED_CROSS1/2  [LED_603]
LED11.39  LED_CROSS1/2  [LED_603]
LED11.40  LED_CROSS1/2  [LED_603]
LED11.41  LED_CROSS1/2  [LED_603]
LED11.42  LED_CROSS1/2  [LED_603]
LED11.43  LED_CROSS1/2  [LED_603]
LED11.44  LED_CROSS1/2  [LED_603]
LED11.45  LED_CROSS1/2  [LED_603]
LED11.46  LED_CROSS1/2  [LED_603]
LED11.47  LED_CROSS1/2  [LED_603]
LED11.48  LED_CROSS1/2  [LED_603]
LED11.49  LED_CROSS1/2  [LED_603]
LED11.50  LED_CROSS1/2  [LED_603]
LED11.51  LED_CROSS1/2  [LED_603]
LED11.52  LED_CROSS1/2  [LED_603]
LED11.53  LED_CROSS1/2  [LED_603]
LED11.54  LED_CROSS1/2  [LED_603]
LED11.55  LED_CROSS1/2  [LED_603]
LED11.56  LED_CROSS1/2  [LED_603]
LED11.57  LED_CROSS1/2  [LED_603]
LED11.58  LED_CROSS1/2  [LED_603]
LED11.59  LED_CROSS1/2  [LED_603]
LED11.60  LED_CROSS1/2  [LED_603]
LED11.61  LED_CROSS1/2  [LED_603]
LED11.62  LED_CROSS1/2  [LED_603]
LED11.63  LED_CROSS1/2  [LED_603]
LED12.0  LED_CROSS1/2  [LED_603]
LED12.1  LED_CROSS1/2  [LED_603]
LED12.2  LED_CROSS1/2  [LED_603]
LED12.3  LED_CROSS1/2  [LED_603]
LED12.4  LED_CROSS1/2  [LED_603]
LED12.5  LED_CROSS1/2  [LED_603]
LED12.6  LED_CROSS1/2  [LED_603]
LED12.7  LED_CROSS1/2  [LED_603]
LED12.8  LED_CROSS1/2  [LED_603]
LED12.9  LED_CROSS1/2  [LED_603]
LED12.10  LED_CROSS1/2  [LED_603]
LED12.11  LED_CROSS1/2  [LED_603]
LED12.12  LED_CROSS1/2  [LED_603]
LED12.13  LED_CROSS1/2  [LED_603]
LED12.14  LED_CROSS1/2  [LED_603]
LED12.15  LED_CROSS1/2  [LED_603]
LED12.16  LED_CROSS1/2  [LED_603]
LED12.17  LED_CROSS1/2  [LED_603]
LED12.18  LED_CROSS1/2  [LED_603]
LED12.19  LED_CROSS1/2  [LED_603]
LED12.20  LED_CROSS1/2  [LED_603]
LED12.21  LED_CROSS1/2  [LED_603]
LED12.22  LED_CROSS1/2  [LED_603]
LED12.23  LED_CROSS1/2  [LED_603]
LED12.24  LED_CROSS1/2  [LED_603]
LED12.25  LED_CROSS1/2  [LED_603]
LED12.26  LED_CROSS1/2  [LED_603]
LED12.27  LED_CROSS1/2  [LED_603]
LED12.28  LED_CROSS1/2  [LED_603]
LED12.29  LED_CROSS1/2  [LED_603]
LED12.30  LED_CROSS1/2  [LED_603]
LED12.31  LED_CROSS1/2  [LED_603]
LED12.32  LED_CROSS1/2  [LED_603]
LED12.33  LED_CROSS1/2  [LED_603]
LED12.34  LED_CROSS1/2  [LED_603]
LED12.35  LED_CROSS1/2  [LED_603]
LED12.36  LED_CROSS1/2  [LED_603]
LED12.37  LED_CROSS1/2  [LED_603]
LED12.38  LED_CROSS1/2  [LED_603]
LED12.39  LED_CROSS1/2  [LED_603]
LED12.40  LED_CROSS1/2  [LED_603]
LED12.41  LED_CROSS1/2  [LED_603]
LED12.42  LED_CROSS1/2  [LED_603]
LED12.43  LED_CROSS1/2  [LED_603]
LED12.44  LED_CROSS1/2  [LED_603]
LED12.45  LED_CROSS1/2  [LED_603]
LED12.46  LED_CROSS1/2  [LED_603]
LED12.47  LED_CROSS1/2  [LED_603]
LED12.48  LED_CROSS1/2  [LED_603]
LED12.49  LED_CROSS1/2  [LED_603]
LED12.50  LED_CROSS1/2  [LED_603]
LED12.51  LED_CROSS1/2  [LED_603]
LED12.52  LED_CROSS1/2  [LED_603]
LED12.53  LED_CROSS1/2  [LED_603]
LED12.54  LED_CROSS1/2  [LED_603]
LED12.55  LED_CROSS1/2  [LED_603]
LED12.56  LED_CROSS1/2  [LED_603]
LED12.57  LED_CROSS1/2  [LED_603]
LED12.58  LED_CROSS1/2  [LED_603]
LED12.59  LED_CROSS1/2  [LED_603]
LED12.60  LED_CROSS1/2  [LED_603]
LED12.61  LED_CROSS1/2  [LED_603]
LED12.62  LED_CROSS1/2  [LED_603]
LED12.63  LED_CROSS1/2  [LED_603]
LED13.0  LED_CROSS1/2  [LED_603]
LED13.1  LED_CROSS1/2  [LED_603]
LED13.2  LED_CROSS1/2  [LED_603]
LED13.3  LED_CROSS1/2  [LED_603]
LED13.4  LED_CROSS1/2  [LED_603]
LED13.5  LED_CROSS1/2  [LED_603]
LED13.6  LED_CROSS1/2  [LED_603]
LED13.7  LED_CROSS1/2  [LED_603]
LED13.8  LED_CROSS1/2  [LED_603]
LED13.9  LED_CROSS1/2  [LED_603]
LED13.10  LED_CROSS1/2  [LED_603]
LED13.11  LED_CROSS1/2  [LED_603]
LED13.12  LED_CROSS1/2  [LED_603]
LED13.13  LED_CROSS1/2  [LED_603]
LED13.14  LED_CROSS1/2  [LED_603]
LED13.15  LED_CROSS1/2  [LED_603]
LED13.16  LED_CROSS1/2  [LED_603]
LED13.17  LED_CROSS1/2  [LED_603]
LED13.18  LED_CROSS1/2  [LED_603]
LED13.19  LED_CROSS1/2  [LED_603]
LED13.20  LED_CROSS1/2  [LED_603]
LED13.21  LED_CROSS1/2  [LED_603]
LED13.22  LED_CROSS1/2  [LED_603]
LED13.23  LED_CROSS1/2  [LED_603]
LED13.24  LED_CROSS1/2  [LED_603]
LED13.25  LED_CROSS1/2  [LED_603]
LED13.26  LED_CROSS1/2  [LED_603]
LED13.27  LED_CROSS1/2  [LED_603]
LED13.28  LED_CROSS1/2  [LED_603]
LED13.29  LED_CROSS1/2  [LED_603]
LED13.30  LED_CROSS1/2  [LED_603]
LED13.31  LED_CROSS1/2  [LED_603]
LED13.32  LED_CROSS1/2  [LED_603]
LED13.33  LED_CROSS1/2  [LED_603]
LED13.34  LED_CROSS1/2  [LED_603]
LED13.35  LED_CROSS1/2  [LED_603]
LED13.36  LED_CROSS1/2  [LED_603]
LED13.37  LED_CROSS1/2  [LED_603]
LED13.38  LED_CROSS1/2  [LED_603]
LED13.39  LED_CROSS1/2  [LED_603]
LED13.40  LED_CROSS1/2  [LED_603]
LED13.41  LED_CROSS1/2  [LED_603]
LED13.42  LED_CROSS1/2  [LED_603]
LED13.43  LED_CROSS1/2  [LED_603]
LED13.44  LED_CROSS1/2  [LED_603]
LED13.45  LED_CROSS1/2  [LED_603]
LED13.46  LED_CROSS1/2  [LED_603]
LED13.47  LED_CROSS1/2  [LED_603]
LED13.48  LED_CROSS1/2  [LED_603]
LED13.49  LED_CROSS1/2  [LED_603]
LED13.50  LED_CROSS1/2  [LED_603]
LED13.51  LED_CROSS1/2  [LED_603]
LED13.52  LED_CROSS1/2  [LED_603]
LED13.53  LED_CROSS1/2  [LED_603]
LED13.54  LED_CROSS1/2  [LED_603]
LED13.55  LED_CROSS1/2  [LED_603]
LED13.56  LED_CROSS1/2  [LED_603]
LED13.57  LED_CROSS1/2  [LED_603]
LED13.58  LED_CROSS1/2  [LED_603]
LED13.59  LED_CROSS1/2  [LED_603]
LED13.60  LED_CROSS1/2  [LED_603]
LED13.61  LED_CROSS1/2  [LED_603]
LED13.62  LED_CROSS1/2  [LED_603]
LED13.63  LED_CROSS1/2  [LED_603]
LED14.0  LED_CROSS1/2  [LED_603]
LED14.1  LED_CROSS1/2  [LED_603]
LED14.2  LED_CROSS1/2  [LED_603]
LED14.3  LED_CROSS1/2  [LED_603]
LED14.4  LED_CROSS1/2  [LED_603]
LED14.5  LED_CROSS1/2  [LED_603]
LED14.6  LED_CROSS1/2  [LED_603]
LED14.7  LED_CROSS1/2  [LED_603]
LED14.8  LED_CROSS1/2  [LED_603]
LED14.9  LED_CROSS1/2  [LED_603]
LED14.10  LED_CROSS1/2  [LED_603]
LED14.11  LED_CROSS1/2  [LED_603]
LED14.12  LED_CROSS1/2  [LED_603]
LED14.13  LED_CROSS1/2  [LED_603]
LED14.14  LED_CROSS1/2  [LED_603]
LED14.15  LED_CROSS1/2  [LED_603]
LED14.16  LED_CROSS1/2  [LED_603]
LED14.17  LED_CROSS1/2  [LED_603]
LED14.18  LED_CROSS1/2  [LED_603]
LED14.19  LED_CROSS1/2  [LED_603]
LED14.20  LED_CROSS1/2  [LED_603]
LED14.21  LED_CROSS1/2  [LED_603]
LED14.22  LED_CROSS1/2  [LED_603]
LED14.23  LED_CROSS1/2  [LED_603]
LED14.24  LED_CROSS1/2  [LED_603]
LED14.25  LED_CROSS1/2  [LED_603]
LED14.26  LED_CROSS1/2  [LED_603]
LED14.27  LED_CROSS1/2  [LED_603]
LED14.28  LED_CROSS1/2  [LED_603]
LED14.29  LED_CROSS1/2  [LED_603]
LED14.30  LED_CROSS1/2  [LED_603]
LED14.31  LED_CROSS1/2  [LED_603]
LED14.32  LED_CROSS1/2  [LED_603]
LED14.33  LED_CROSS1/2  [LED_603]
LED14.34  LED_CROSS1/2  [LED_603]
LED14.35  LED_CROSS1/2  [LED_603]
LED14.36  LED_CROSS1/2  [LED_603]
LED14.37  LED_CROSS1/2  [LED_603]
LED14.38  LED_CROSS1/2  [LED_603]
LED14.39  LED_CROSS1/2  [LED_603]
LED14.40  LED_CROSS1/2  [LED_603]
LED14.41  LED_CROSS1/2  [LED_603]
LED14.42  LED_CROSS1/2  [LED_603]
LED14.43  LED_CROSS1/2  [LED_603]
LED14.44  LED_CROSS1/2  [LED_603]
LED14.45  LED_CROSS1/2  [LED_603]
LED14.46  LED_CROSS1/2  [LED_603]
LED14.47  LED_CROSS1/2  [LED_603]
LED14.48  LED_CROSS1/2  [LED_603]
LED14.49  LED_CROSS1/2  [LED_603]
LED14.50  LED_CROSS1/2  [LED_603]
LED14.51  LED_CROSS1/2  [LED_603]
LED14.52  LED_CROSS1/2  [LED_603]
LED14.53  LED_CROSS1/2  [LED_603]
LED14.54  LED_CROSS1/2  [LED_603]
LED14.55  LED_CROSS1/2  [LED_603]
LED14.56  LED_CROSS1/2  [LED_603]
LED14.57  LED_CROSS1/2  [LED_603]
LED14.58  LED_CROSS1/2  [LED_603]
LED14.59  LED_CROSS1/2  [LED_603]
LED14.60  LED_CROSS1/2  [LED_603]
LED14.61  LED_CROSS1/2  [LED_603]
LED14.62  LED_CROSS1/2  [LED_603]
LED14.63  LED_CROSS1/2  [LED_603]
LED15.0  LED_CROSS1/2  [LED_603]
LED15.1  LED_CROSS1/2  [LED_603]
LED15.2  LED_CROSS1/2  [LED_603]
LED15.3  LED_CROSS1/2  [LED_603]
LED15.4  LED_CROSS1/2  [LED_603]
LED15.5  LED_CROSS1/2  [LED_603]
LED15.6  LED_CROSS1/2  [LED_603]
LED15.7  LED_CROSS1/2  [LED_603]
LED15.8  LED_CROSS1/2  [LED_603]
LED15.9  LED_CROSS1/2  [LED_603]
LED15.10  LED_CROSS1/2  [LED_603]
LED15.11  LED_CROSS1/2  [LED_603]
LED15.12  LED_CROSS1/2  [LED_603]
LED15.13  LED_CROSS1/2  [LED_603]
LED15.14  LED_CROSS1/2  [LED_603]
LED15.15  LED_CROSS1/2  [LED_603]
LED15.16  LED_CROSS1/2  [LED_603]
LED15.17  LED_CROSS1/2  [LED_603]
LED15.18  LED_CROSS1/2  [LED_603]
LED15.19  LED_CROSS1/2  [LED_603]
LED15.20  LED_CROSS1/2  [LED_603]
LED15.21  LED_CROSS1/2  [LED_603]
LED15.22  LED_CROSS1/2  [LED_603]
LED15.23  LED_CROSS1/2  [LED_603]
LED15.24  LED_CROSS1/2  [LED_603]
LED15.25  LED_CROSS1/2  [LED_603]
LED15.26  LED_CROSS1/2  [LED_603]
LED15.27  LED_CROSS1/2  [LED_603]
LED15.28  LED_CROSS1/2  [LED_603]
LED15.29  LED_CROSS1/2  [LED_603]
LED15.30  LED_CROSS1/2  [LED_603]
LED15.31  LED_CROSS1/2  [LED_603]
LED15.32  LED_CROSS1/2  [LED_603]
LED15.33  LED_CROSS1/2  [LED_603]
LED15.34  LED_CROSS1/2  [LED_603]
LED15.35  LED_CROSS1/2  [LED_603]
LED15.36  LED_CROSS1/2  [LED_603]
LED15.37  LED_CROSS1/2  [LED_603]
LED15.38  LED_CROSS1/2  [LED_603]
LED15.39  LED_CROSS1/2  [LED_603]
LED15.40  LED_CROSS1/2  [LED_603]
LED15.41  LED_CROSS1/2  [LED_603]
LED15.42  LED_CROSS1/2  [LED_603]
LED15.43  LED_CROSS1/2  [LED_603]
LED15.44  LED_CROSS1/2  [LED_603]
LED15.45  LED_CROSS1/2  [LED_603]
LED15.46  LED_CROSS1/2  [LED_603]
LED15.47  LED_CROSS1/2  [LED_603]
LED15.48  LED_CROSS1/2  [LED_603]
LED15.49  LED_CROSS1/2  [LED_603]
LED15.50  LED_CROSS1/2  [LED_603]
LED15.51  LED_CROSS1/2  [LED_603]
LED15.52  LED_CROSS1/2  [LED_603]
LED15.53  LED_CROSS1/2  [LED_603]
LED15.54  LED_CROSS1/2  [LED_603]
LED15.55  LED_CROSS1/2  [LED_603]
LED15.56  LED_CROSS1/2  [LED_603]
LED15.57  LED_CROSS1/2  [LED_603]
LED15.58  LED_CROSS1/2  [LED_603]
LED15.59  LED_CROSS1/2  [LED_603]
LED15.60  LED_CROSS1/2  [LED_603]
LED15.61  LED_CROSS1/2  [LED_603]
LED15.62  LED_CROSS1/2  [LED_603]
LED15.63  LED_CROSS1/2  [LED_603]
LED16.0  LED_CROSS1/2  [LED_603]
LED16.1  LED_CROSS1/2  [LED_603]
LED16.2  LED_CROSS1/2  [LED_603]
LED16.3  LED_CROSS1/2  [LED_603]
LED16.4  LED_CROSS1/2  [LED_603]
LED16.5  LED_CROSS1/2  [LED_603]
LED16.6  LED_CROSS1/2  [LED_603]
LED16.7  LED_CROSS1/2  [LED_603]
LED16.8  LED_CROSS1/2  [LED_603]
LED16.9  LED_CROSS1/2  [LED_603]
LED16.10  LED_CROSS1/2  [LED_603]
LED16.11  LED_CROSS1/2  [LED_603]
LED16.12  LED_CROSS1/2  [LED_603]
LED16.13  LED_CROSS1/2  [LED_603]
LED16.14  LED_CROSS1/2  [LED_603]
LED16.15  LED_CROSS1/2  [LED_603]
LED16.16  LED_CROSS1/2  [LED_603]
LED16.17  LED_CROSS1/2  [LED_603]
LED16.18  LED_CROSS1/2  [LED_603]
LED16.19  LED_CROSS1/2  [LED_603]
LED16.20  LED_CROSS1/2  [LED_603]
LED16.21  LED_CROSS1/2  [LED_603]
LED16.22  LED_CROSS1/2  [LED_603]
LED16.23  LED_CROSS1/2  [LED_603]
LED16.24  LED_CROSS1/2  [LED_603]
LED16.25  LED_CROSS1/2  [LED_603]
LED16.26  LED_CROSS1/2  [LED_603]
LED16.27  LED_CROSS1/2  [LED_603]
LED16.28  LED_CROSS1/2  [LED_603]
LED16.29  LED_CROSS1/2  [LED_603]
LED16.30  LED_CROSS1/2  [LED_603]
LED16.31  LED_CROSS1/2  [LED_603]
LED16.32  LED_CROSS1/2  [LED_603]
LED16.33  LED_CROSS1/2  [LED_603]
LED16.34  LED_CROSS1/2  [LED_603]
LED16.35  LED_CROSS1/2  [LED_603]
LED16.36  LED_CROSS1/2  [LED_603]
LED16.37  LED_CROSS1/2  [LED_603]
LED16.38  LED_CROSS1/2  [LED_603]
LED16.39  LED_CROSS1/2  [LED_603]
LED16.40  LED_CROSS1/2  [LED_603]
LED16.41  LED_CROSS1/2  [LED_603]
LED16.42  LED_CROSS1/2  [LED_603]
LED16.43  LED_CROSS1/2  [LED_603]
LED16.44  LED_CROSS1/2  [LED_603]
LED16.45  LED_CROSS1/2  [LED_603]
LED16.46  LED_CROSS1/2  [LED_603]
LED16.47  LED_CROSS1/2  [LED_603]
LED16.48  LED_CROSS1/2  [LED_603]
LED16.49  LED_CROSS1/2  [LED_603]
LED16.50  LED_CROSS1/2  [LED_603]
LED16.51  LED_CROSS1/2  [LED_603]
LED16.52  LED_CROSS1/2  [LED_603]
LED16.53  LED_CROSS1/2  [LED_603]
LED16.54  LED_CROSS1/2  [LED_603]
LED16.55  LED_CROSS1/2  [LED_603]
LED16.56  LED_CROSS1/2  [LED_603]
LED16.57  LED_CROSS1/2  [LED_603]
LED16.58  LED_CROSS1/2  [LED_603]
LED16.59  LED_CROSS1/2  [LED_603]
LED16.60  LED_CROSS1/2  [LED_603]
LED16.61  LED_CROSS1/2  [LED_603]
LED16.62  LED_CROSS1/2  [LED_603]
LED16.63  LED_CROSS1/2  [LED_603]
LED17.0  LED_CROSS1/2  [LED_603]
LED17.1  LED_CROSS1/2  [LED_603]
LED17.2  LED_CROSS1/2  [LED_603]
LED17.3  LED_CROSS1/2  [LED_603]
LED17.4  LED_CROSS1/2  [LED_603]
LED17.5  LED_CROSS1/2  [LED_603]
LED17.6  LED_CROSS1/2  [LED_603]
LED17.7  LED_CROSS1/2  [LED_603]
LED17.8  LED_CROSS1/2  [LED_603]
LED17.9  LED_CROSS1/2  [LED_603]
LED17.10  LED_CROSS1/2  [LED_603]
LED17.11  LED_CROSS1/2  [LED_603]
LED17.12  LED_CROSS1/2  [LED_603]
LED17.13  LED_CROSS1/2  [LED_603]
LED17.14  LED_CROSS1/2  [LED_603]
LED17.15  LED_CROSS1/2  [LED_603]
LED17.16  LED_CROSS1/2  [LED_603]
LED17.17  LED_CROSS1/2  [LED_603]
LED17.18  LED_CROSS1/2  [LED_603]
LED17.19  LED_CROSS1/2  [LED_603]
LED17.20  LED_CROSS1/2  [LED_603]
LED17.21  LED_CROSS1/2  [LED_603]
LED17.22  LED_CROSS1/2  [LED_603]
LED17.23  LED_CROSS1/2  [LED_603]
LED17.24  LED_CROSS1/2  [LED_603]
LED17.25  LED_CROSS1/2  [LED_603]
LED17.26  LED_CROSS1/2  [LED_603]
LED17.27  LED_CROSS1/2  [LED_603]
LED17.28  LED_CROSS1/2  [LED_603]
LED17.29  LED_CROSS1/2  [LED_603]
LED17.30  LED_CROSS1/2  [LED_603]
LED17.31  LED_CROSS1/2  [LED_603]
LED17.32  LED_CROSS1/2  [LED_603]
LED17.33  LED_CROSS1/2  [LED_603]
LED17.34  LED_CROSS1/2  [LED_603]
LED17.35  LED_CROSS1/2  [LED_603]
LED17.36  LED_CROSS1/2  [LED_603]
LED17.37  LED_CROSS1/2  [LED_603]
LED17.38  LED_CROSS1/2  [LED_603]
LED17.39  LED_CROSS1/2  [LED_603]
LED17.40  LED_CROSS1/2  [LED_603]
LED17.41  LED_CROSS1/2  [LED_603]
LED17.42  LED_CROSS1/2  [LED_603]
LED17.43  LED_CROSS1/2  [LED_603]
LED17.44  LED_CROSS1/2  [LED_603]
LED17.45  LED_CROSS1/2  [LED_603]
LED17.46  LED_CROSS1/2  [LED_603]
LED17.47  LED_CROSS1/2  [LED_603]
LED17.48  LED_CROSS1/2  [LED_603]
LED17.49  LED_CROSS1/2  [LED_603]
LED17.50  LED_CROSS1/2  [LED_603]
LED17.51  LED_CROSS1/2  [LED_603]
LED17.52  LED_CROSS1/2  [LED_603]
LED17.53  LED_CROSS1/2  [LED_603]
LED17.54  LED_CROSS1/2  [LED_603]
LED17.55  LED_CROSS1/2  [LED_603]
LED17.56  LED_CROSS1/2  [LED_603]
LED17.57  LED_CROSS1/2  [LED_603]
LED17.58  LED_CROSS1/2  [LED_603]
LED17.59  LED_CROSS1/2  [LED_603]
LED17.60  LED_CROSS1/2  [LED_603]
LED17.61  LED_CROSS1/2  [LED_603]
LED17.62  LED_CROSS1/2  [LED_603]
LED17.63  LED_CROSS1/2  [LED_603]
LED18.0  LED_CROSS1/2  [LED_603]
LED18.1  LED_CROSS1/2  [LED_603]
LED18.2  LED_CROSS1/2  [LED_603]
LED18.3  LED_CROSS1/2  [LED_603]
LED18.4  LED_CROSS1/2  [LED_603]
LED18.5  LED_CROSS1/2  [LED_603]
LED18.6  LED_CROSS1/2  [LED_603]
LED18.7  LED_CROSS1/2  [LED_603]
LED18.8  LED_CROSS1/2  [LED_603]
LED18.9  LED_CROSS1/2  [LED_603]
LED18.10  LED_CROSS1/2  [LED_603]
LED18.11  LED_CROSS1/2  [LED_603]
LED18.12  LED_CROSS1/2  [LED_603]
LED18.13  LED_CROSS1/2  [LED_603]
LED18.14  LED_CROSS1/2  [LED_603]
LED18.15  LED_CROSS1/2  [LED_603]
LED18.16  LED_CROSS1/2  [LED_603]
LED18.17  LED_CROSS1/2  [LED_603]
LED18.18  LED_CROSS1/2  [LED_603]
LED18.19  LED_CROSS1/2  [LED_603]
LED18.20  LED_CROSS1/2  [LED_603]
LED18.21  LED_CROSS1/2  [LED_603]
LED18.22  LED_CROSS1/2  [LED_603]
LED18.23  LED_CROSS1/2  [LED_603]
LED18.24  LED_CROSS1/2  [LED_603]
LED18.25  LED_CROSS1/2  [LED_603]
LED18.26  LED_CROSS1/2  [LED_603]
LED18.27  LED_CROSS1/2  [LED_603]
LED18.28  LED_CROSS1/2  [LED_603]
LED18.29  LED_CROSS1/2  [LED_603]
LED18.30  LED_CROSS1/2  [LED_603]
LED18.31  LED_CROSS1/2  [LED_603]
LED18.32  LED_CROSS1/2  [LED_603]
LED18.33  LED_CROSS1/2  [LED_603]
LED18.34  LED_CROSS1/2  [LED_603]
LED18.35  LED_CROSS1/2  [LED_603]
LED18.36  LED_CROSS1/2  [LED_603]
LED18.37  LED_CROSS1/2  [LED_603]
LED18.38  LED_CROSS1/2  [LED_603]
LED18.39  LED_CROSS1/2  [LED_603]
LED18.40  LED_CROSS1/2  [LED_603]
LED18.41  LED_CROSS1/2  [LED_603]
LED18.42  LED_CROSS1/2  [LED_603]
LED18.43  LED_CROSS1/2  [LED_603]
LED18.44  LED_CROSS1/2  [LED_603]
LED18.45  LED_CROSS1/2  [LED_603]
LED18.46  LED_CROSS1/2  [LED_603]
LED18.47  LED_CROSS1/2  [LED_603]
LED18.48  LED_CROSS1/2  [LED_603]
LED18.49  LED_CROSS1/2  [LED_603]
LED18.50  LED_CROSS1/2  [LED_603]
LED18.51  LED_CROSS1/2  [LED_603]
LED18.52  LED_CROSS1/2  [LED_603]
LED18.53  LED_CROSS1/2  [LED_603]
LED18.54  LED_CROSS1/2  [LED_603]
LED18.55  LED_CROSS1/2  [LED_603]
LED18.56  LED_CROSS1/2  [LED_603]
LED18.57  LED_CROSS1/2  [LED_603]
LED18.58  LED_CROSS1/2  [LED_603]
LED18.59  LED_CROSS1/2  [LED_603]
LED18.60  LED_CROSS1/2  [LED_603]
LED18.61  LED_CROSS1/2  [LED_603]
LED18.62  LED_CROSS1/2  [LED_603]
LED18.63  LED_CROSS1/2  [LED_603]
LED19.0  LED_CROSS1/2  [LED_603]
LED19.1  LED_CROSS1/2  [LED_603]
LED19.2  LED_CROSS1/2  [LED_603]
LED19.3  LED_CROSS1/2  [LED_603]
LED19.4  LED_CROSS1/2  [LED_603]
LED19.5  LED_CROSS1/2  [LED_603]
LED19.6  LED_CROSS1/2  [LED_603]
LED19.7  LED_CROSS1/2  [LED_603]
LED19.8  LED_CROSS1/2  [LED_603]
LED19.9  LED_CROSS1/2  [LED_603]
LED19.10  LED_CROSS1/2  [LED_603]
LED19.11  LED_CROSS1/2  [LED_603]
LED19.12  LED_CROSS1/2  [LED_603]
LED19.13  LED_CROSS1/2  [LED_603]
LED19.14  LED_CROSS1/2  [LED_603]
LED19.15  LED_CROSS1/2  [LED_603]
LED19.16  LED_CROSS1/2  [LED_603]
LED19.17  LED_CROSS1/2  [LED_603]
LED19.18  LED_CROSS1/2  [LED_603]
LED19.19  LED_CROSS1/2  [LED_603]
LED19.20  LED_CROSS1/2  [LED_603]
LED19.21  LED_CROSS1/2  [LED_603]
LED19.22  LED_CROSS1/2  [LED_603]
LED19.23  LED_CROSS1/2  [LED_603]
LED19.24  LED_CROSS1/2  [LED_603]
LED19.25  LED_CROSS1/2  [LED_603]
LED19.26  LED_CROSS1/2  [LED_603]
LED19.27  LED_CROSS1/2  [LED_603]
LED19.28  LED_CROSS1/2  [LED_603]
LED19.29  LED_CROSS1/2  [LED_603]
LED19.30  LED_CROSS1/2  [LED_603]
LED19.31  LED_CROSS1/2  [LED_603]
LED19.32  LED_CROSS1/2  [LED_603]
LED19.33  LED_CROSS1/2  [LED_603]
LED19.34  LED_CROSS1/2  [LED_603]
LED19.35  LED_CROSS1/2  [LED_603]
LED19.36  LED_CROSS1/2  [LED_603]
LED19.37  LED_CROSS1/2  [LED_603]
LED19.38  LED_CROSS1/2  [LED_603]
LED19.39  LED_CROSS1/2  [LED_603]
LED19.40  LED_CROSS1/2  [LED_603]
LED19.41  LED_CROSS1/2  [LED_603]
LED19.42  LED_CROSS1/2  [LED_603]
LED19.43  LED_CROSS1/2  [LED_603]
LED19.44  LED_CROSS1/2  [LED_603]
LED19.45  LED_CROSS1/2  [LED_603]
LED19.46  LED_CROSS1/2  [LED_603]
LED19.47  LED_CROSS1/2  [LED_603]
LED19.48  LED_CROSS1/2  [LED_603]
LED19.49  LED_CROSS1/2  [LED_603]
LED19.50  LED_CROSS1/2  [LED_603]
LED19.51  LED_CROSS1/2  [LED_603]
LED19.52  LED_CROSS1/2  [LED_603]
LED19.53  LED_CROSS1/2  [LED_603]
LED19.54  LED_CROSS1/2  [LED_603]
LED19.55  LED_CROSS1/2  [LED_603]
LED19.56  LED_CROSS1/2  [LED_603]
LED19.57  LED_CROSS1/2  [LED_603]
LED19.58  LED_CROSS1/2  [LED_603]
LED19.59  LED_CROSS1/2  [LED_603]
LED19.60  LED_CROSS1/2  [LED_603]
LED19.61  LED_CROSS1/2  [LED_603]
LED19.62  LED_CROSS1/2  [LED_603]
LED19.63  LED_CROSS1/2  [LED_603]
LED20.0  LED_CROSS1/2  [LED_603]
LED20.1  LED_CROSS1/2  [LED_603]
LED20.2  LED_CROSS1/2  [LED_603]
LED20.3  LED_CROSS1/2  [LED_603]
LED20.4  LED_CROSS1/2  [LED_603]
LED20.5  LED_CROSS1/2  [LED_603]
LED20.6  LED_CROSS1/2  [LED_603]
LED20.7  LED_CROSS1/2  [LED_603]
LED20.8  LED_CROSS1/2  [LED_603]
LED20.9  LED_CROSS1/2  [LED_603]
LED20.10  LED_CROSS1/2  [LED_603]
LED20.11  LED_CROSS1/2  [LED_603]
LED20.12  LED_CROSS1/2  [LED_603]
LED20.13  LED_CROSS1/2  [LED_603]
LED20.14  LED_CROSS1/2  [LED_603]
LED20.15  LED_CROSS1/2  [LED_603]
LED20.16  LED_CROSS1/2  [LED_603]
LED20.17  LED_CROSS1/2  [LED_603]
LED20.18  LED_CROSS1/2  [LED_603]
LED20.19  LED_CROSS1/2  [LED_603]
LED20.20  LED_CROSS1/2  [LED_603]
LED20.21  LED_CROSS1/2  [LED_603]
LED20.22  LED_CROSS1/2  [LED_603]
LED20.23  LED_CROSS1/2  [LED_603]
LED20.24  LED_CROSS1/2  [LED_603]
LED20.25  LED_CROSS1/2  [LED_603]
LED20.26  LED_CROSS1/2  [LED_603]
LED20.27  LED_CROSS1/2  [LED_603]
LED20.28  LED_CROSS1/2  [LED_603]
LED20.29  LED_CROSS1/2  [LED_603]
LED20.30  LED_CROSS1/2  [LED_603]
LED20.31  LED_CROSS1/2  [LED_603]
LED20.32  LED_CROSS1/2  [LED_603]
LED20.33  LED_CROSS1/2  [LED_603]
LED20.34  LED_CROSS1/2  [LED_603]
LED20.35  LED_CROSS1/2  [LED_603]
LED20.36  LED_CROSS1/2  [LED_603]
LED20.37  LED_CROSS1/2  [LED_603]
LED20.38  LED_CROSS1/2  [LED_603]
LED20.39  LED_CROSS1/2  [LED_603]
LED20.40  LED_CROSS1/2  [LED_603]
LED20.41  LED_CROSS1/2  [LED_603]
LED20.42  LED_CROSS1/2  [LED_603]
LED20.43  LED_CROSS1/2  [LED_603]
LED20.44  LED_CROSS1/2  [LED_603]
LED20.45  LED_CROSS1/2  [LED_603]
LED20.46  LED_CROSS1/2  [LED_603]
LED20.47  LED_CROSS1/2  [LED_603]
LED20.48  LED_CROSS1/2  [LED_603]
LED20.49  LED_CROSS1/2  [LED_603]
LED20.50  LED_CROSS1/2  [LED_603]
LED20.51  LED_CROSS1/2  [LED_603]
LED20.52  LED_CROSS1/2  [LED_603]
LED20.53  LED_CROSS1/2  [LED_603]
LED20.54  LED_CROSS1/2  [LED_603]
LED20.55  LED_CROSS1/2  [LED_603]
LED20.56  LED_CROSS1/2  [LED_603]
LED20.57  LED_CROSS1/2  [LED_603]
LED20.58  LED_CROSS1/2  [LED_603]
LED20.59  LED_CROSS1/2  [LED_603]
LED20.60  LED_CROSS1/2  [LED_603]
LED20.61  LED_CROSS1/2  [LED_603]
LED20.62  LED_CROSS1/2  [LED_603]
LED20.63  LED_CROSS1/2  [LED_603]
LED21.0  LED_CROSS1/2  [LED_603]
LED21.1  LED_CROSS1/2  [LED_603]
LED21.2  LED_CROSS1/2  [LED_603]
LED21.3  LED_CROSS1/2  [LED_603]
LED21.4  LED_CROSS1/2  [LED_603]
LED21.5  LED_CROSS1/2  [LED_603]
LED21.6  LED_CROSS1/2  [LED_603]
LED21.7  LED_CROSS1/2  [LED_603]
LED21.8  LED_CROSS1/2  [LED_603]
LED21.9  LED_CROSS1/2  [LED_603]
LED21.10  LED_CROSS1/2  [LED_603]
LED21.11  LED_CROSS1/2  [LED_603]
LED21.12  LED_CROSS1/2  [LED_603]
LED21.13  LED_CROSS1/2  [LED_603]
LED21.14  LED_CROSS1/2  [LED_603]
LED21.15  LED_CROSS1/2  [LED_603]
LED21.16  LED_CROSS1/2  [LED_603]
LED21.17  LED_CROSS1/2  [LED_603]
LED21.18  LED_CROSS1/2  [LED_603]
LED21.19  LED_CROSS1/2  [LED_603]
LED21.20  LED_CROSS1/2  [LED_603]
LED21.21  LED_CROSS1/2  [LED_603]
LED21.22  LED_CROSS1/2  [LED_603]
LED21.23  LED_CROSS1/2  [LED_603]
LED21.24  LED_CROSS1/2  [LED_603]
LED21.25  LED_CROSS1/2  [LED_603]
LED21.26  LED_CROSS1/2  [LED_603]
LED21.27  LED_CROSS1/2  [LED_603]
LED21.28  LED_CROSS1/2  [LED_603]
LED21.29  LED_CROSS1/2  [LED_603]
LED21.30  LED_CROSS1/2  [LED_603]
LED21.31  LED_CROSS1/2  [LED_603]
LED21.32  LED_CROSS1/2  [LED_603]
LED21.33  LED_CROSS1/2  [LED_603]
LED21.34  LED_CROSS1/2  [LED_603]
LED21.35  LED_CROSS1/2  [LED_603]
LED21.36  LED_CROSS1/2  [LED_603]
LED21.37  LED_CROSS1/2  [LED_603]
LED21.38  LED_CROSS1/2  [LED_603]
LED21.39  LED_CROSS1/2  [LED_603]
LED21.40  LED_CROSS1/2  [LED_603]
LED21.41  LED_CROSS1/2  [LED_603]
LED21.42  LED_CROSS1/2  [LED_603]
LED21.43  LED_CROSS1/2  [LED_603]
LED21.44  LED_CROSS1/2  [LED_603]
LED21.45  LED_CROSS1/2  [LED_603]
LED21.46  LED_CROSS1/2  [LED_603]
LED21.47  LED_CROSS1/2  [LED_603]
LED21.48  LED_CROSS1/2  [LED_603]
LED21.49  LED_CROSS1/2  [LED_603]
LED21.50  LED_CROSS1/2  [LED_603]
LED21.51  LED_CROSS1/2  [LED_603]
LED21.52  LED_CROSS1/2  [LED_603]
LED21.53  LED_CROSS1/2  [LED_603]
LED21.54  LED_CROSS1/2  [LED_603]
LED21.55  LED_CROSS1/2  [LED_603]
LED21.56  LED_CROSS1/2  [LED_603]
LED21.57  LED_CROSS1/2  [LED_603]
LED21.58  LED_CROSS1/2  [LED_603]
LED21.59  LED_CROSS1/2  [LED_603]
LED21.60  LED_CROSS1/2  [LED_603]
LED21.61  LED_CROSS1/2  [LED_603]
LED21.62  LED_CROSS1/2  [LED_603]
LED21.63  LED_CROSS1/2  [LED_603]
X0  PAD_PIN  [PAD0.012]
X1  PAD_PIN  [PAD0.012]
X2  PAD_PIN  [PAD0.012]
X3  PAD_PIN  [PAD0.012]
X4  PAD_PIN  [PAD0.012]
X5  PAD_PIN  [PAD0.012]
X6  PAD_PIN  [PAD0.012]
X7  PAD_PIN  [PAD0.012]
X8  PAD_PIN  [PAD0.012]
X9  PAD_PIN  [PAD0.012]
X10  PAD_PIN  [PAD0.012]
X11  PAD_PIN  [PAD0.012]
X12  PAD_PIN  [PAD0.012]
X13  PAD_PIN  [PAD0.012]
X14  PAD_PIN  [PAD0.012]
X15  PAD_PIN  [PAD0.012]
X16  PAD_PIN  [PAD0.012]
X17  PAD_PIN  [PAD0.012]
X18  PAD_PIN  [PAD0.012]
X19  PAD_PIN  [PAD0.012]
X20  PAD_PIN  [PAD0.012]
X21  PAD_PIN  [PAD0.012]
X22  PAD_PIN  [PAD0.012]
X23  PAD_PIN  [PAD0.012]
X24  PAD_PIN  [PAD0.012]
X25  PAD_PIN  [PAD0.012]
X26  PAD_PIN  [PAD0.012]
X27  PAD_PIN  [PAD0.012]
X28  PAD_PIN  [PAD0.012]
X29  PAD_PIN  [PAD0.012]
X30  PAD_PIN  [PAD0.012]
X31  PAD_PIN  [PAD0.012]
X32  PAD_PIN  [PAD0.012]
X33  PAD_PIN  [PAD0.012]
X34  PAD_PIN  [PAD0.012]
X35  PAD_PIN  [PAD0.012]
X36  PAD_PIN  [PAD0.012]
X37  PAD_PIN  [PAD0.012]
X38  PAD_PIN  [PAD0.012]
X39  PAD_PIN  [PAD0.012]
X40  PAD_PIN  [PAD0.012]
X41  PAD_PIN  [PAD0.012]
X42  PAD_PIN  [PAD0.012]
X43  PAD_PIN  [PAD0.012]
X44  PAD_PIN  [PAD0.012]
X45  PAD_PIN  [PAD0.012]
X46  PAD_PIN  [PAD0.012]
X47  PAD_PIN  [PAD0.012]
X48  PAD_PIN  [PAD0.012]
X49  PAD_PIN  [PAD0.012]
X50  PAD_PIN  [PAD0.012]
X51  PAD_PIN  [PAD0.012]
X52  PAD_PIN  [PAD0.012]
X53  PAD_PIN  [PAD0.012]
X54  PAD_PIN  [PAD0.012]
X55  PAD_PIN  [PAD0.012]
X56  PAD_PIN  [PAD0.012]
X57  PAD_PIN  [PAD0.012]
X58  PAD_PIN  [PAD0.012]
X59  PAD_PIN  [PAD0.012]
X60  PAD_PIN  [PAD0.012]
X61  PAD_PIN  [PAD0.012]
X62  PAD_PIN  [PAD0.012]
X63  PAD_PIN  [PAD0.012]
Y.0  PAD_PIN  [PAD0.012]
Y.1  PAD_PIN  [PAD0.012]
Y.2  PAD_PIN  [PAD0.012]
Y.3  PAD_PIN  [PAD0.012]
Y.4  PAD_PIN  [PAD0.012]
Y.5  PAD_PIN  [PAD0.012]
Y.6  PAD_PIN  [PAD0.012]
Y.7  PAD_PIN  [PAD0.012]
Y.8  PAD_PIN  [PAD0.012]
Y.9  PAD_PIN  [PAD0.012]
Y.10  PAD_PIN  [PAD0.012]
Y.11  PAD_PIN  [PAD0.012]
Y.12  PAD_PIN  [PAD0.012]
Y.13  PAD_PIN  [PAD0.012]
Y.14  PAD_PIN  [PAD0.012]
Y.15  PAD_PIN  [PAD0.012]
Y.16  PAD_PIN  [PAD0.012]
Y.17  PAD_PIN  [PAD0.012]
Y.18  PAD_PIN  [PAD0.012]
Y.19  PAD_PIN  [PAD0.012]
Y.20  PAD_PIN  [PAD0.012]
Y.21  PAD_PIN  [PAD0.012]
